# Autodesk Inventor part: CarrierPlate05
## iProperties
Created: 2008-02
Part Number: CarrierPlate05
Document SubType Name: Modeling
Designer: grh
Density: 1 g/cm^3
Author: grh
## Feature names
1. Extrusion1
